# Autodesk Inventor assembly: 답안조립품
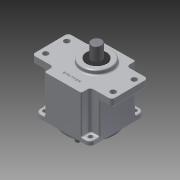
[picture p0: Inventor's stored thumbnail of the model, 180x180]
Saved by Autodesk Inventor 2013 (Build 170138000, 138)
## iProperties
Created: 2015-07
Part Number: 답안조립품
Document SubType Name: Assembly
Designer: user
Author: user
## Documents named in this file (12)
- C:\Users\user\Desktop\450734V1019\답안조립품.iam
- C:\Users\user\Desktop\450734V1019\본체.ipt
- C:\Users\user\Desktop\450734V1019\서브축.ipt
- C:\Users\user\Desktop\450734V1019\베어링 608.ipt
- 베어링 608.ipt
- C:\Users\user\Desktop\450734V1019\베어링 6003.ipt
- 베어링 6003.ipt
- C:\Users\user\Desktop\450734V1019\커버.ipt
- C:\Users\user\Desktop\450734V1019\메인축.ipt
- C:\Users\user\Desktop\450734V1019\오일실 17x32x8.ipt
- C:\Users\user\Desktop\450734V1019\오일실 8x22x7.ipt
- C:\Users\user\Desktop\450734V1019\M4x0.5x16.ipt
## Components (4 placed, 1 different names)
1. M4x0.5x12:1
2. M4x0.5x12:2
3. M4x0.5x12:3
4. M4x0.5x12:4
